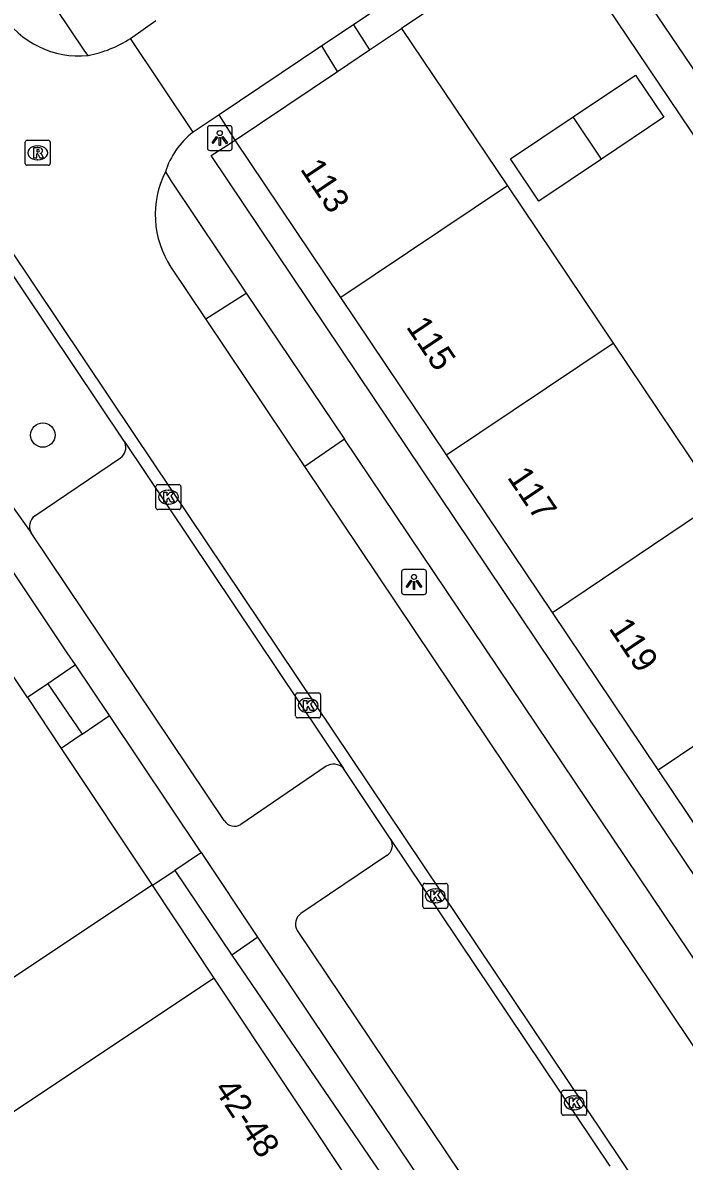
# Model space of a CAD drawing. Extents: x 158797 to 159887, y 384318 to 385255.
# Drawn here: x 159138.91 to 159165.46, y 384630.65 to 384676.36 of the extents above; entities that cross this region are included whole.
import ezdxf

# ---------------------------------------------------------------- set-up
doc = ezdxf.new("R2010")
doc.units = 0
for name, color, linetype in [('IMGEO_Boom', 7, 'Continuous'), ('IMGEO_Erf', 7, 'Continuous'), ('IMGEO_Groenvoorziening', 7, 'Continuous'), ('IMGEO_Kolk', 7, 'Continuous'), ('IMGEO_Lichtpunt', 7, 'Continuous'), ('IMGEO_Pand', 7, 'Continuous'), ('IMGEO_Pand_nummerreeks', 7, 'Continuous'), ('IMGEO_Parkeervlak_halfverhard', 7, 'Continuous'), ('IMGEO_Parkeervlak_open', 7, 'Continuous'), ('IMGEO_Rijbaan_lokaal_open', 7, 'Continuous'), ('IMGEO_Rioolput', 7, 'Continuous'), ('IMGEO_Voetpad_op_trap', 7, 'Continuous'), ('IMGEO_Voetpad_open', 7, 'Continuous')]:
    doc.layers.add(name, color=color, linetype=linetype)

msp = doc.modelspace()

# ---------------------------------------------------------------- linework, layer by layer
at = {"layer": 'IMGEO_Boom'}
msp.add_circle((159139.714, 384659.808), 0.489, dxfattribs=at)
at = {"layer": 'IMGEO_Erf'}
msp.add_lwpolyline([(159144.107, 384641.742), (159144.112, 384641.735)], dxfattribs=at)
at = {"layer": 'IMGEO_Groenvoorziening'}
msp.add_lwpolyline([(159160.216, 384680.233), (159154.114, 384676.135)], dxfattribs=at)
at = {"layer": 'IMGEO_Kolk'}
for p, q in [((159144.254, 384656.893), (159144.254, 384657.745)), ((159144.329, 384657.819), (159145.181, 384657.819)), ((159145.255, 384657.745), (159145.255, 384656.893)), ((159144.742, 384657.599), (159144.767, 384657.599)), ((159145.181, 384656.819), (159144.329, 384656.819)), ((159144.765, 384657.039), (159144.74, 384657.039)), ((159149.936, 384649.456), (159150.788, 384649.456)), ((159149.861, 384648.53), (159149.861, 384649.382)), ((159150.349, 384649.236), (159150.374, 384649.236)), ((159150.862, 384649.382), (159150.862, 384648.53)), ((159150.372, 384648.676), (159150.347, 384648.676)), ((159150.788, 384648.456), (159149.936, 384648.456)), ((159154.968, 384640.881), (159154.968, 384641.733)), ((159155.043, 384641.807), (159155.895, 384641.807)), ((159155.969, 384641.733), (159155.969, 384640.881)), ((159155.456, 384641.587), (159155.481, 384641.587)), ((159155.895, 384640.807), (159155.043, 384640.807)), ((159155.479, 384641.027), (159155.454, 384641.027)), ((159160.614, 384633.502), (159161.466, 384633.502)), ((159160.539, 384632.576), (159160.539, 384633.428)), ((159161.027, 384633.282), (159161.052, 384633.282)), ((159161.54, 384633.428), (159161.54, 384632.576)), ((159161.05, 384632.722), (159161.025, 384632.722)), ((159161.466, 384632.502), (159160.614, 384632.502))]:
    msp.add_line(p, q, dxfattribs=at)
for points in [[(159144.254, 384656.893), (159144.254, 384657.745)], [(159144.329, 384657.819), (159145.181, 384657.819)], [(159145.255, 384657.745), (159145.255, 384656.893)], [(159144.575, 384657.519), (159144.698, 384657.519), (159144.698, 384657.368), (159144.828, 384657.519), (159144.992, 384657.519), (159144.846, 384657.368), (159144.999, 384657.119), (159144.847, 384657.119), (159144.762, 384657.283), (159144.698, 384657.216), (159144.698, 384657.119), (159144.575, 384657.119), (159144.575, 384657.519)], [(159145.181, 384656.819), (159144.329, 384656.819)], [(159149.936, 384649.456), (159150.788, 384649.456)], [(159149.861, 384648.53), (159149.861, 384649.382)], [(159150.182, 384649.156), (159150.305, 384649.156), (159150.305, 384649.005), (159150.435, 384649.156), (159150.599, 384649.156), (159150.453, 384649.005), (159150.606, 384648.756), (159150.454, 384648.756), (159150.369, 384648.92), (159150.305, 384648.853), (159150.305, 384648.756), (159150.182, 384648.756), (159150.182, 384649.156)], [(159150.862, 384649.382), (159150.862, 384648.53)], [(159150.788, 384648.456), (159149.936, 384648.456)], [(159154.968, 384640.881), (159154.968, 384641.733)], [(159155.043, 384641.807), (159155.895, 384641.807)], [(159155.969, 384641.733), (159155.969, 384640.881)], [(159155.289, 384641.507), (159155.412, 384641.507), (159155.412, 384641.356), (159155.542, 384641.507), (159155.706, 384641.507), (159155.56, 384641.356), (159155.713, 384641.107), (159155.561, 384641.107), (159155.476, 384641.271), (159155.412, 384641.204), (159155.412, 384641.107), (159155.289, 384641.107), (159155.289, 384641.507)], [(159155.895, 384640.807), (159155.043, 384640.807)], [(159160.614, 384633.502), (159161.466, 384633.502)], [(159160.539, 384632.576), (159160.539, 384633.428)], [(159160.86, 384633.202), (159160.983, 384633.202), (159160.983, 384633.051), (159161.113, 384633.202), (159161.277, 384633.202), (159161.131, 384633.051), (159161.284, 384632.802), (159161.132, 384632.802), (159161.047, 384632.966), (159160.983, 384632.899), (159160.983, 384632.802), (159160.86, 384632.802), (159160.86, 384633.202)], [(159161.54, 384633.428), (159161.54, 384632.576)], [(159161.466, 384632.502), (159160.614, 384632.502)]]:
    msp.add_lwpolyline(points, dxfattribs=at)
for centre, start, end in [((159144.331, 384657.743), 91.552, 178.448), ((159144.331, 384657.743), 91.552, 178.448), ((159145.179, 384657.743), 1.552, 88.448), ((159145.179, 384657.743), 1.552, 88.448), ((159144.331, 384656.895), 181.552, 268.448), ((159144.331, 384656.895), 181.552, 268.448), ((159145.179, 384656.895), 271.552, 358.448), ((159145.179, 384656.895), 271.552, 358.448), ((159149.938, 384649.38), 91.552, 178.448), ((159149.938, 384649.38), 91.552, 178.448), ((159150.786, 384649.38), 1.552, 88.448), ((159150.786, 384649.38), 1.552, 88.448), ((159149.938, 384648.532), 181.552, 268.448), ((159149.938, 384648.532), 181.552, 268.448), ((159150.786, 384648.532), 271.552, 358.448), ((159150.786, 384648.532), 271.552, 358.448), ((159155.045, 384641.731), 91.552, 178.448), ((159155.045, 384641.731), 91.552, 178.448), ((159155.893, 384641.731), 1.552, 88.448), ((159155.893, 384641.731), 1.552, 88.448), ((159155.045, 384640.883), 181.552, 268.448), ((159155.045, 384640.883), 181.552, 268.448), ((159155.893, 384640.883), 271.552, 358.448), ((159155.893, 384640.883), 271.552, 358.448), ((159160.616, 384633.426), 91.552, 178.448), ((159160.616, 384633.426), 91.552, 178.448), ((159161.464, 384633.426), 1.552, 88.448), ((159161.464, 384633.426), 1.552, 88.448), ((159160.616, 384632.578), 181.552, 268.448), ((159160.616, 384632.578), 181.552, 268.448), ((159161.464, 384632.578), 271.552, 358.448), ((159161.464, 384632.578), 271.552, 358.448)]:
    msp.add_arc(centre, 0.0765, start, end, dxfattribs=at)
for centre, major_axis, ratio, start_param, end_param in [((159144.741, 384657.319), (-0.387, 0.002), 0.722429, 4.712389, 7.853982), ((159144.766, 384657.319), (-0.39, 0.002), 0.717154, 1.570796, 4.712389), ((159150.348, 384648.956), (-0.387, 0.002), 0.722429, 4.712389, 7.853982), ((159150.373, 384648.956), (-0.39, 0.002), 0.717154, 1.570796, 4.712389), ((159155.455, 384641.307), (-0.387, 0.002), 0.722429, 4.712389, 7.853982), ((159155.48, 384641.307), (-0.39, 0.002), 0.717154, 1.570796, 4.712389), ((159161.026, 384633.002), (-0.387, 0.002), 0.722429, 4.712389, 7.853982), ((159161.051, 384633.002), (-0.39, 0.002), 0.717154, 1.570796, 4.712389)]:
    msp.add_ellipse(centre, major_axis=major_axis, ratio=ratio, start_param=start_param, end_param=end_param, dxfattribs=at)
at = {"layer": 'IMGEO_Lichtpunt'}
for p, q in [((159146.318, 384672.135), (159146.318, 384671.328)), ((159146.318, 384672.135), (159146.318, 384671.328)), ((159147.22, 384672.23), (159146.412, 384672.23)), ((159147.22, 384672.23), (159146.412, 384672.23)), ((159147.314, 384671.328), (159147.314, 384672.135)), ((159147.314, 384671.328), (159147.314, 384672.135)), ((159146.412, 384671.234), (159147.22, 384671.234)), ((159146.412, 384671.234), (159147.22, 384671.234)), ((159154.115, 384654.315), (159154.115, 384653.508)), ((159154.115, 384654.315), (159154.115, 384653.508)), ((159155.017, 384654.41), (159154.209, 384654.41)), ((159155.017, 384654.41), (159154.209, 384654.41)), ((159155.111, 384653.508), (159155.111, 384654.315)), ((159155.111, 384653.508), (159155.111, 384654.315)), ((159154.209, 384653.414), (159155.017, 384653.414)), ((159154.209, 384653.414), (159155.017, 384653.414))]:
    msp.add_line(p, q, dxfattribs=at)
for points in [[(159146.692, 384671.799), (159146.731, 384671.771), (159146.543, 384671.509), (159146.505, 384671.536), (159146.692, 384671.799)], [(159146.794, 384671.751), (159146.841, 384671.751), (159146.841, 384671.429), (159146.794, 384671.429), (159146.794, 384671.751)], [(159146.904, 384671.771), (159146.942, 384671.798), (159147.129, 384671.536), (159147.09, 384671.508), (159146.904, 384671.771)], [(159154.489, 384653.979), (159154.528, 384653.951), (159154.34, 384653.689), (159154.302, 384653.716), (159154.489, 384653.979)], [(159154.591, 384653.931), (159154.638, 384653.931), (159154.638, 384653.609), (159154.591, 384653.609), (159154.591, 384653.931)], [(159154.701, 384653.951), (159154.739, 384653.978), (159154.926, 384653.716), (159154.887, 384653.688), (159154.701, 384653.951)]]:
    msp.add_lwpolyline(points, dxfattribs=at)
for centre in [(159146.817, 384671.933), (159154.614, 384654.113)]:
    msp.add_circle(centre, 0.0994, dxfattribs=at)
for centre, start, end in [((159146.412, 384672.135), 90, 180), ((159146.412, 384672.135), 90, 180), ((159147.22, 384672.135), 0, 90), ((159147.22, 384672.135), 0, 90), ((159146.412, 384671.328), 180, 270), ((159146.412, 384671.328), 180, 270), ((159147.22, 384671.328), 270, 0), ((159147.22, 384671.328), 270, 360), ((159154.209, 384654.315), 90, 180), ((159154.209, 384654.315), 90, 180), ((159155.017, 384654.315), 0, 90), ((159155.017, 384654.315), 0, 90), ((159154.209, 384653.508), 180, 270), ((159154.209, 384653.508), 180, 270), ((159155.017, 384653.508), 270, 0), ((159155.017, 384653.508), 270, 360)]:
    msp.add_arc(centre, 0.0946, start, end, dxfattribs=at)
at = {"layer": 'IMGEO_Pand'}
for points in [[(159168.046, 384685.528), (159161.396, 384681.061), (159166.005, 384674.237)], [(159152.829, 384675.272), (159154.114, 384676.135)], [(159154.114, 384676.135), (159158.36, 384669.818)], [(159151.548, 384674.412), (159152.829, 384675.272)], [(159147.433, 384671.648), (159151.548, 384674.412)], [(159160.999, 384672.58), (159163.508, 384674.261), (159164.643, 384672.566), (159162.134, 384670.885)], [(159162.134, 384670.885), (159159.624, 384669.204), (159158.489, 384670.899), (159160.999, 384672.58)], [(159162.134, 384670.885), (159160.999, 384672.58)], [(159151.678, 384665.329), (159147.433, 384671.648)], [(159158.36, 384669.818), (159151.678, 384665.329)], [(159158.36, 384669.818), (159162.607, 384663.5)], [(159155.924, 384659.01), (159151.678, 384665.329)], [(159155.924, 384659.01), (159162.607, 384663.5)], [(159162.607, 384663.5), (159166.854, 384657.182)], [(159160.169, 384652.691), (159155.924, 384659.01)], [(159160.169, 384652.691), (159166.854, 384657.182)], [(159139.092, 384649.275), (159135.451, 384654.745), (159110.182, 384637.924), (159118.838, 384624.921)], [(159164.414, 384646.371), (159160.169, 384652.691)], [(159164.414, 384646.371), (159171.101, 384650.864)], [(159139.092, 384649.275), (159140.454, 384647.229)], [(159140.454, 384647.229), (159144.107, 384641.742)], [(159168.66, 384640.052), (159164.414, 384646.371)], [(159144.107, 384641.742), (159118.838, 384624.921)], [(159146.597, 384638.002), (159121.328, 384621.181)], [(159152.616, 384628.959), (159146.597, 384638.002)]]:
    msp.add_lwpolyline(points, dxfattribs=at)
at = {"layer": 'IMGEO_Parkeervlak_halfverhard'}
for points in [[(159146.259, 384664.469), (159147.882, 384665.51)], [(159151.826, 384659.643), (159150.227, 384658.552)]]:
    msp.add_lwpolyline(points, dxfattribs=at)
at = {"layer": 'IMGEO_Parkeervlak_open'}
for points in [[(159143.015, 384659.487), (159142.977, 384659.569)], [(159139.387, 384656.562), (159142.831, 384658.894)]]:
    msp.add_lwpolyline(points, dxfattribs=at)
for centre, radius, start, end in [((159142.536, 384659.311), 0.51, 305.2924, 20.2307), ((159139.7, 384656.14), 0.525, 126.5692, 209.091)]:
    msp.add_arc(centre, radius, start, end, dxfattribs=at)
at = {"layer": 'IMGEO_Rijbaan_lokaal_open'}
for points in [[(159159.55, 384681.239), (159152.18, 384676.285)], [(159143.234, 384675.735), (159144.25, 384676.451)], [(159152.18, 384676.285), (159150.917, 384675.437)], [(159145.743, 384671.966), (159143.234, 384675.735)], [(159150.917, 384675.437), (159146.794, 384672.665)], [(159142.977, 384659.569), (159132.904, 384674.594)], [(159133.301, 384674.864), (159143.376, 384659.836), (159169.474, 384620.932)], [(159146.794, 384672.665), (159145.743, 384671.966)], [(159146.259, 384664.469), (159144.859, 384666.556)], [(159150.227, 384658.552), (159146.259, 384664.469)], [(159142.977, 384659.569), (159151.786, 384646.421)], [(159167.157, 384633.31), (159150.227, 384658.552)], [(159153.675, 384643.594), (159153.659, 384643.618), (159151.816, 384646.386), (159151.786, 384646.421)], [(159162.493, 384630.457), (159153.675, 384643.594)]]:
    msp.add_lwpolyline(points, dxfattribs=at)
for centre, radius, start, end in [((159141.175, 384678.74), 3.709, 212.7786, 275.4984), ((159140.604, 384679.802), 4.843, 281.0239, 302.8917), ((159147.74, 384669.387), 3.262, 127.7599, 162.2996), ((159148.052, 384668.663), 3.826, 153.3489, 213.4175)]:
    msp.add_arc(centre, radius, start, end, dxfattribs=at)
at = {"layer": 'IMGEO_Rioolput'}
for p, q in [((159139.007, 384670.716), (159139.007, 384671.568)), ((159139.082, 384671.642), (159139.934, 384671.642)), ((159139.495, 384671.422), (159139.52, 384671.422)), ((159140.008, 384671.568), (159140.008, 384670.716)), ((159139.934, 384670.642), (159139.082, 384670.642)), ((159139.518, 384670.862), (159139.493, 384670.862))]:
    msp.add_line(p, q, dxfattribs=at)
for points in [[(159139.007, 384670.716), (159139.007, 384671.568)], [(159139.082, 384671.642), (159139.934, 384671.642)], [(159140.008, 384671.568), (159140.008, 384670.716)], [(159139.596, 384671.34), (159139.344, 384671.342), (159139.344, 384670.942)], [(159139.344, 384670.942), (159139.468, 384670.942), (159139.468, 384671.104), (159139.479, 384671.104)], [(159139.522, 384671.261), (159139.468, 384671.261), (159139.468, 384671.18)], [(159139.468, 384671.18), (159139.52, 384671.18)], [(159139.526, 384671.075), (159139.597, 384670.942), (159139.737, 384670.942), (159139.672, 384671.068)], [(159139.934, 384670.642), (159139.082, 384670.642)]]:
    msp.add_lwpolyline(points, dxfattribs=at)
for centre, radius, start, end in [((159139.084, 384671.566), 0.0765, 91.552, 178.448), ((159139.084, 384671.566), 0.0765, 91.552, 178.448), ((159139.932, 384671.566), 0.0765, 1.552, 88.448), ((159139.932, 384671.566), 0.0765, 1.552, 88.448), ((159139.478, 384671.051), 0.0533, 26.0293, 88.6989), ((159139.504, 384671.369), 0.19, 274.7715, 282.9687), ((159139.528, 384671.165), 0.0964, 77.0061, 93.1865), ((159139.542, 384671.222), 0.0378, 276.6634, 79.6772), ((159139.595, 384671.23), 0.109, 350.3612, 89.416), ((159139.593, 384671.23), 0.112, 277.5842, 350.9817), ((159139.577, 384671.015), 0.108, 29.5134, 73.7905), ((159139.084, 384670.718), 0.0765, 181.552, 268.448), ((159139.084, 384670.718), 0.0765, 181.552, 268.448), ((159139.932, 384670.718), 0.0765, 271.552, 358.448), ((159139.932, 384670.718), 0.0765, 271.552, 358.448)]:
    msp.add_arc(centre, radius, start, end, dxfattribs=at)
for centre, major_axis, ratio, start_param, end_param in [((159139.494, 384671.142), (-0.387, 0.002), 0.722429, 4.712389, 7.853982), ((159139.519, 384671.142), (-0.39, 0.002), 0.717154, 1.570796, 4.712389)]:
    msp.add_ellipse(centre, major_axis=major_axis, ratio=ratio, start_param=start_param, end_param=end_param, dxfattribs=at)
at = {"layer": 'IMGEO_Voetpad_op_trap'}
for points in [[(159141.021, 384650.58), (159139.909, 384649.828)], [(159141.292, 384647.8), (159142.385, 384648.546)], [(159146.077, 384643.044), (159145.014, 384642.329)], [(159148.35, 384639.651), (159147.302, 384638.927)]]:
    msp.add_lwpolyline(points, dxfattribs=at)
at = {"layer": 'IMGEO_Voetpad_open'}
for points in [[(159141.53, 384675.048), (159141.397, 384675.222), (159125.586, 384698.761)], [(159185.666, 384642.429), (159160.216, 384680.233)], [(159152.18, 384676.285), (159152.829, 384675.272)], [(159151.548, 384674.412), (159150.917, 384675.437)], [(159147.433, 384671.648), (159146.794, 384672.665)], [(159172.905, 384633.733), (159171.93, 384633.091), (159146.474, 384671.034), (159147.433, 384671.648)], [(159144.633, 384670.379), (159144.861, 384670.004), (159147.882, 384665.51)], [(159147.882, 384665.51), (159151.826, 384659.643)], [(159170.662, 384631.666), (159170.315, 384632.138), (159151.826, 384659.643)], [(159136.246, 384658.77), (159136.871, 384659.186), (159139.241, 384655.885)], [(159141.021, 384650.58), (159140.693, 384651.069), (159138.492, 384654.363), (159137.276, 384656.161), (159136.677, 384657.042), (159107.897, 384637.647)], [(159146.994, 384644.33), (159139.241, 384655.885)], [(159142.385, 384648.546), (159141.021, 384650.58)], [(159139.909, 384649.828), (159139.092, 384649.275)], [(159139.909, 384649.828), (159141.292, 384647.8)], [(159146.077, 384643.044), (159146.044, 384643.093), (159142.385, 384648.546)], [(159141.292, 384647.8), (159140.454, 384647.229)], [(159151.091, 384646.51), (159147.661, 384644.178)], [(159153.675, 384643.594), (159153.682, 384643.582), (159153.689, 384643.569)], [(159148.35, 384639.651), (159146.077, 384643.044)], [(159153.519, 384642.929), (159150.075, 384640.599)], [(159144.112, 384641.735), (159145.014, 384642.329)], [(159145.014, 384642.329), (159147.302, 384638.927)], [(159146.597, 384638.002), (159144.112, 384641.735)], [(159149.922, 384639.92), (159157.675, 384628.378)], [(159153.662, 384629.631), (159154.621, 384630.291), (159148.35, 384639.651)], [(159147.302, 384638.927), (159152.988, 384630.591), (159153.662, 384629.631)]]:
    msp.add_lwpolyline(points, dxfattribs=at)
for centre, radius, start, end in [((159151.385, 384646.05), 0.546, 42.7722, 122.633), ((159147.405, 384644.593), 0.488, 212.6684, 301.6562), ((159153.26, 384643.34), 0.486, 302.1574, 28.0913), ((159150.362, 384640.178), 0.51, 124.2826, 210.3205)]:
    msp.add_arc(centre, radius, start, end, dxfattribs=at)

# ---------------------------------------------------------------- texts
at = {"layer": 'IMGEO_Pand_nummerreeks'}
for s, rotation, p in [('113', 303.896, (159150.019, 384670.488)), ('115', 303.896, (159154.274, 384664.155)), ('117', 303.896, (159158.33, 384658.117)), ('119', 303.896, (159162.406, 384652.049)), ('42-48', 303.6496, (159146.555, 384633.553))]:
    msp.add_text(s, height=1, rotation=rotation, dxfattribs=at).set_placement(p)

doc.saveas('drawing.dxf')
